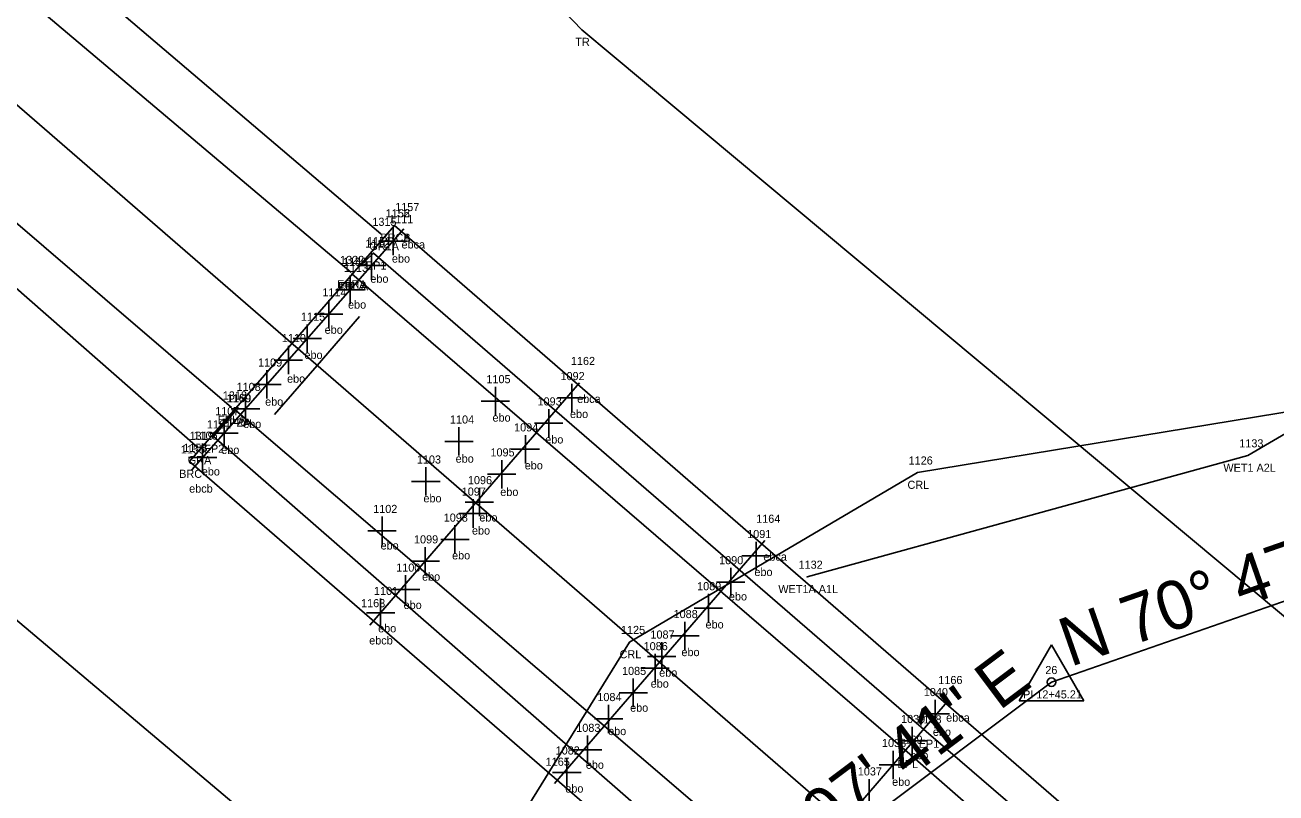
# Model space of a CAD drawing. Extents: x 2085293 to 2087464, y 876528 to 879458.
# Drawn here: x 2086332.2 to 2086486.4, y 878514.7 to 878609.3 of the extents above; entities that cross this region are included whole.
import ezdxf

# ---------------------------------------------------------------- set-up
doc = ezdxf.new("R2010")
doc.units = 0
for name, color, linetype in [('RD_EX_Bridge', 7, 'Continuous'), ('RD_EX_Bridge_txCode', 7, 'Continuous'), ('RD_EX_GuardRail', 7, 'Continuous'), ('RD_EX_GuardRail_txCode', 7, 'Continuous'), ('RD_EX_H2O', 7, 'Continuous'), ('RD_EX_H2O_txCode', 7, 'Continuous'), ('RD_EX_H2O_WetLd', 7, 'Continuous'), ('RD_EX_H2O_WetLd_txCode', 7, 'Continuous'), ('RD_EX_Misc', 7, 'Continuous'), ('RD_EX_Misc_txCode', 7, 'Continuous'), ('RD_EX_Road', 7, 'Continuous'), ('RD_EX_Road_txCode', 7, 'Continuous'), ('RD_EX_VEG', 7, 'Continuous'), ('RD_EX_VEG_txCode', 7, 'Continuous'), ('RD_HC_Cl', 7, 'Continuous'), ('RD_HC_Data', 7, 'Continuous'), ('RD_HC_Data_Tic', 7, 'Continuous'), ('RD_HC_txCode', 7, 'Continuous'), ('RD_SMD_Locator', 7, 'Continuous')]:
    doc.layers.add(name, color=color, linetype=linetype)

msp = doc.modelspace()

# ---------------------------------------------------------------- linework, layer by layer
at = {"layer": 'RD_EX_Bridge'}
msp.add_lwpolyline([(2086377.74, 878584.61), (2086559.01, 878427.4), (2086533.93, 878398.26), (2086352.47, 878555.51), (2086377.74, 878584.61)], dxfattribs=at)
at = {"layer": 'RD_EX_GuardRail'}
msp.add_line((2086353.55, 878557.19), (2086197.14, 878694.36), dxfattribs=at)
msp.add_lwpolyline([(2086376.08, 878583.56), (2086298.41, 878649.65), (2086246.79, 878694.55)], dxfattribs=at)
at = {"layer": 'RD_EX_H2O'}
msp.add_lwpolyline([(2086350.1, 878485.82), (2086392.62, 878510.5), (2086406.71, 878533.27), (2086442.18, 878554.15), (2086494.98, 878562.84), (2086530.51, 878595.43), (2086576.04, 878629.72), (2086651.92, 878628.48)], dxfattribs=at)
at = {"layer": 'RD_EX_H2O_WetLd'}
msp.add_lwpolyline([(2086428.59, 878541.31), (2086482.9, 878556.26), (2086496.03, 878563.96), (2086512.46, 878581.4)], dxfattribs=at)
at = {"layer": 'RD_EX_Misc'}
for p, q in [((2086378.89, 878584.18), (2086352.78, 878554.51)), ((2086377.57, 878584.43), (2086377.57, 878580.93)), ((2086374.93, 878581.43), (2086374.93, 878577.93)), ((2086379.32, 878582.68), (2086375.82, 878582.68)), ((2086372.29, 878578.43), (2086372.29, 878574.93)), ((2086376.68, 878579.68), (2086373.18, 878579.68)), ((2086369.64, 878575.42), (2086369.64, 878571.92)), ((2086374.04, 878576.68), (2086370.54, 878576.68)), ((2086367, 878572.42), (2086367, 878568.92)), ((2086371.39, 878573.67), (2086367.89, 878573.67)), ((2086368.75, 878570.67), (2086365.25, 878570.67)), ((2086364.68, 878569.78), (2086364.68, 878566.28)), ((2086366.43, 878568.03), (2086362.93, 878568.03)), ((2086362.03, 878566.77), (2086362.03, 878563.27)), ((2086363.78, 878565.02), (2086360.28, 878565.02)), ((2086400.56, 878565.21), (2086374.71, 878535.37)), ((2086390.18, 878564.72), (2086390.18, 878561.22)), ((2086399.59, 878565.1), (2086399.59, 878561.6)), ((2086359.39, 878563.77), (2086359.39, 878560.27)), ((2086391.93, 878562.97), (2086388.43, 878562.97)), ((2086401.34, 878563.35), (2086397.84, 878563.35)), ((2086361.14, 878562.02), (2086357.64, 878562.02)), ((2086396.75, 878561.98), (2086396.75, 878558.48)), ((2086356.75, 878560.77), (2086356.75, 878557.27)), ((2086398.5, 878560.23), (2086395, 878560.23)), ((2086358.5, 878559.02), (2086355, 878559.02)), ((2086385.69, 878559.75), (2086385.69, 878556.25)), ((2086393.87, 878558.78), (2086393.87, 878555.28)), ((2086354.11, 878557.76), (2086354.11, 878554.26)), ((2086387.44, 878558), (2086383.94, 878558)), ((2086395.62, 878557.03), (2086392.12, 878557.03)), ((2086355.86, 878556.01), (2086352.36, 878556.01)), ((2086390.96, 878555.7), (2086390.96, 878552.2)), ((2086381.61, 878554.82), (2086381.61, 878551.32)), ((2086392.71, 878553.95), (2086389.21, 878553.95)), ((2086383.36, 878553.07), (2086379.86, 878553.07)), ((2086388.2, 878552.28), (2086388.2, 878548.78)), ((2086387.42, 878550.87), (2086387.42, 878547.37)), ((2086389.17, 878549.12), (2086385.67, 878549.12)), ((2086389.95, 878550.53), (2086386.45, 878550.53)), ((2086376.22, 878548.73), (2086376.22, 878545.23)), ((2086385.2, 878547.66), (2086385.2, 878544.16)), ((2086377.97, 878546.98), (2086374.47, 878546.98)), ((2086381.53, 878544.98), (2086381.53, 878541.48)), ((2086386.95, 878545.91), (2086383.45, 878545.91)), ((2086423.39, 878545.77), (2086397.46, 878515.83)), ((2086422.3, 878545.64), (2086422.3, 878542.14)), ((2086383.28, 878543.23), (2086379.78, 878543.23)), ((2086424.05, 878543.89), (2086420.55, 878543.89)), ((2086379.11, 878541.5), (2086379.11, 878538)), ((2086419.17, 878542.41), (2086419.17, 878538.91)), ((2086420.92, 878540.66), (2086417.42, 878540.66)), ((2086376.04, 878538.63), (2086376.04, 878535.13)), ((2086380.86, 878539.75), (2086377.36, 878539.75)), ((2086416.42, 878539.21), (2086416.42, 878535.71)), ((2086377.79, 878536.88), (2086374.29, 878536.88)), ((2086418.17, 878537.46), (2086414.67, 878537.46)), ((2086413.52, 878535.78), (2086413.52, 878532.28)), ((2086415.27, 878534.03), (2086411.77, 878534.03)), ((2086410.67, 878533.25), (2086410.67, 878529.75)), ((2086412.42, 878531.5), (2086408.92, 878531.5)), ((2086409.85, 878531.82), (2086409.85, 878528.32)), ((2086411.6, 878530.07), (2086408.1, 878530.07)), ((2086407.16, 878528.77), (2086407.16, 878525.27)), ((2086408.91, 878527.02), (2086405.41, 878527.02)), ((2086444.38, 878526.17), (2086444.38, 878522.67)), ((2086404.13, 878525.55), (2086404.13, 878522.05)), ((2086445.86, 878525.9), (2086420.02, 878496.01)), ((2086446.13, 878524.42), (2086442.63, 878524.42)), ((2086405.88, 878523.8), (2086402.38, 878523.8)), ((2086441.54, 878522.85), (2086441.54, 878519.35)), ((2086401.53, 878521.76), (2086401.53, 878518.26)), ((2086403.28, 878520.01), (2086399.78, 878520.01)), ((2086439.2, 878519.89), (2086439.2, 878516.39)), ((2086443.29, 878521.1), (2086439.79, 878521.1)), ((2086398.98, 878518.97), (2086398.98, 878515.47)), ((2086400.73, 878517.22), (2086397.23, 878517.22)), ((2086440.95, 878518.14), (2086437.45, 878518.14)), ((2086436.22, 878516.39), (2086436.22, 878512.89))]:
    msp.add_line(p, q, dxfattribs=at)
at = {"layer": 'RD_EX_Road'}
for points in [[(2086372.38, 878578.86), (2086293.83, 878645.12), (2086244.36, 878687.63), (2086202.39, 878723.25), (2086166.57, 878755.93), (2086121.04, 878795), (2086040.83, 878865.43), (2085975.87, 878922.08), (2085950.22, 878944.06), (2085880.76, 879003.91), (2085804.88, 879069.53), (2085722.05, 879140.46), (2085671.69, 879184.07), (2085652.93, 879200.33), (2085629.96, 879220.25)], [(2086357.65, 878562.16), (2086280.16, 878628.67), (2086188.35, 878708.55), (2086107.57, 878779.2), (2086026.47, 878849.35), (2085949.01, 878917.79), (2085867.99, 878987.21), (2085809.89, 879037.77), (2085792.99, 879052.21), (2085710.02, 879123.37), (2085618.43, 879202.89)], [(2086372.48, 878578.63), (2086375.14, 878581.18), (2086443.25, 878522.25), (2086511.37, 878463.55), (2086556.66, 878424.84), (2086553.57, 878421.17)], [(2086372.48, 878578.63), (2086440.93, 878519.74), (2086508.75, 878460.4), (2086553.57, 878421.17), (2086626.32, 878357.37), (2086700.27, 878293.03), (2086782.28, 878221.68)], [(2086358.19, 878561.82), (2086355.45, 878558.6), (2086422.99, 878499.64), (2086491.68, 878440.33), (2086536.87, 878401.71), (2086539.89, 878405.13)], [(2086358.19, 878561.82), (2086426.45, 878503.36), (2086494.99, 878444.26), (2086539.89, 878405.13), (2086612.82, 878341.2), (2086686.27, 878277.41), (2086769.9, 878205.27), (2086844.45, 878140.34), (2086932.82, 878063.42), (2086964.75, 878034.46), (2087001.42, 877999.16), (2087042.78, 877955.43), (2087078.39, 877914.63), (2087110.34, 877876.43), (2087140.35, 877836.91), (2087173.38, 877789.29), (2087206.69, 877736.44), (2087236.08, 877683.18), (2087259.17, 877638.22), (2087287.12, 877578.12)]]:
    msp.add_lwpolyline(points, dxfattribs=at)
at = {"layer": 'RD_EX_VEG'}
for points in [[(2086498.28, 878394.88), (2086329.73, 878537.22), (2086212.13, 878664.14), (2086102.42, 878763.92), (2085939.19, 878906.04), (2085793.62, 879021.84)], [(2086569.24, 878468.04), (2086400.81, 878608.73), (2086323.2, 878689.41), (2086335.21, 878726.99)]]:
    msp.add_lwpolyline(points, dxfattribs=at)
at = {"layer": 'RD_HC_Cl'}
for p, q in [((2086923.31, 878086.15), (2085624.78, 879211.84)), ((2086458.69, 878528.33), (2086516.79, 878548.57)), ((2086413.25, 878494.25), (2086458.69, 878528.33))]:
    msp.add_line(p, q, dxfattribs=at)
at = {"layer": 'RD_HC_Data'}
for p, q in [((2086454.72, 878526.04), (2086458.69, 878532.92)), ((2086458.69, 878532.92), (2086462.66, 878526.04)), ((2086454.72, 878526.04), (2086462.66, 878526.04))]:
    msp.add_line(p, q, dxfattribs=at)
msp.add_circle((2086458.69, 878528.33), 0.529, dxfattribs=at)
at = {"layer": 'RD_HC_Data_Tic'}
for q in [(2086373.44, 878573.41), (2086362.96, 878561.32)]:
    msp.add_line((2086368.2, 878567.37), q, dxfattribs=at)
at = {"layer": 'RD_SMD_Locator'}
for centre in [(2086400.81, 878608.73), (2086377.74, 878584.61), (2086377.74, 878584.61), (2086376.08, 878583.56), (2086375.14, 878581.18), (2086372.38, 878578.86), (2086372.48, 878578.63), (2086372.48, 878578.63), (2086357.65, 878562.16), (2086358.19, 878561.82), (2086358.19, 878561.82), (2086355.45, 878558.6), (2086353.55, 878557.19), (2086352.47, 878555.51), (2086482.9, 878556.26), (2086442.18, 878554.15), (2086428.59, 878541.31), (2086406.71, 878533.27), (2086458.69, 878528.33), (2086443.25, 878522.25), (2086440.93, 878519.74)]:
    msp.add_circle(centre, 0.001, dxfattribs=at)

# ---------------------------------------------------------------- texts
at = {"layer": 'RD_EX_Bridge_txCode'}
for s, p in [('1156', (2086376.65, 878585.61)), ('1152', (2086376.67, 878585.61)), ('BRCA', (2086376, 878582.61)), ('BRCB', (2086376.01, 878582.61)), ('1155', (2086351.41, 878556.51)), ('BRC', (2086351.22, 878553.51))]:
    msp.add_text(s, height=1, dxfattribs=at).set_placement(p)
at = {"layer": 'RD_EX_GuardRail_txCode'}
for s, p in [('1315', (2086375.02, 878584.56)), ('GR1A', (2086374.65, 878581.56)), ('1319', (2086352.49, 878558.19)), ('GRA', (2086352.28, 878555.19))]:
    msp.add_text(s, height=1, dxfattribs=at).set_placement(p)
at = {"layer": 'RD_EX_H2O_txCode'}
for s, p in [('1126', (2086441.09, 878555.15)), ('CRL', (2086440.95, 878552.15)), ('1125', (2086405.65, 878534.27)), ('CRL', (2086405.48, 878531.27))]:
    msp.add_text(s, height=1, dxfattribs=at).set_placement(p)
at = {"layer": 'RD_EX_H2O_WetLd_txCode'}
for s, p in [('1133', (2086481.83, 878557.26)), ('WET1 A2L', (2086479.87, 878554.26)), ('1132', (2086427.53, 878542.31)), ('WET1A A1L', (2086425.04, 878539.31))]:
    msp.add_text(s, height=1, dxfattribs=at).set_placement(p)
at = {"layer": 'RD_EX_Misc_txCode'}
for s, p in [('1157', (2086377.83, 878586.38)), ('1111', (2086377.08, 878584.88)), ('1112', (2086374.15, 878581.88)), ('ebca', (2086378.61, 878581.77)), ('1113', (2086371.51, 878578.88)), ('ebo', (2086377.43, 878580.03)), ('ebo', (2086374.77, 878577.55)), ('1114', (2086368.86, 878575.87)), ('ebo', (2086372.02, 878574.36)), ('1115', (2086366.22, 878572.87)), ('ebo', (2086369.14, 878571.26)), ('1110', (2086363.86, 878570.23)), ('ebo', (2086366.65, 878568.16)), ('1109', (2086360.93, 878567.22)), ('1162', (2086399.48, 878567.41)), ('ebo', (2086364.51, 878565.23)), ('1105', (2086389.07, 878565.17)), ('1092', (2086398.2, 878565.55)), ('1108', (2086358.29, 878564.22)), ('ebo', (2086361.81, 878562.4)), ('1093', (2086395.37, 878562.43)), ('ebca', (2086400.25, 878562.74)), ('1107', (2086355.65, 878561.22)), ('ebo', (2086389.82, 878560.44)), ('ebo', (2086399.37, 878560.88)), ('ebo', (2086359.1, 878559.65)), ('1104', (2086384.58, 878560.2)), ('1094', (2086392.48, 878559.23)), ('1106', (2086352.98, 878558.21)), ('ebo', (2086396.32, 878557.74)), ('1158', (2086351.72, 878556.71)), ('ebo', (2086356.4, 878556.46)), ('1095', (2086389.57, 878556.15)), ('1103', (2086380.5, 878555.27)), ('ebo', (2086385.28, 878555.38)), ('ebo', (2086393.79, 878554.55)), ('ebo', (2086354, 878553.8)), ('1096', (2086386.79, 878552.73)), ('ebcb', (2086352.45, 878551.69)), ('1097', (2086386.03, 878551.32)), ('ebo', (2086390.78, 878551.28)), ('ebo', (2086381.31, 878550.49)), ('1102', (2086375.12, 878549.18)), ('1098', (2086383.81, 878548.11)), ('ebo', (2086388.2, 878548.13)), ('ebo', (2086387.29, 878546.52)), ('1164', (2086422.31, 878547.97)), ('1099', (2086380.15, 878545.43)), ('1091', (2086421.2, 878546.09)), ('ebo', (2086376.03, 878544.68)), ('ebo', (2086384.84, 878543.46)), ('1100', (2086377.96, 878541.95)), ('1090', (2086417.74, 878542.86)), ('ebca', (2086423.19, 878543.3)), ('ebo', (2086381.14, 878540.84)), ('ebo', (2086422.09, 878541.41)), ('1101', (2086375.22, 878539.08)), ('1089', (2086415.03, 878539.66)), ('1163', (2086373.63, 878537.57)), ('ebo', (2086378.87, 878537.35)), ('ebo', (2086418.95, 878538.4)), ('1088', (2086412.13, 878536.23)), ('ebo', (2086375.73, 878534.47)), ('ebo', (2086416.07, 878534.95)), ('ebcb', (2086374.63, 878532.98)), ('1087', (2086409.28, 878533.7)), ('1086', (2086408.44, 878532.27)), ('ebo', (2086413.1, 878531.54)), ('1085', (2086405.78, 878529.22)), ('ebo', (2086410.36, 878529.01)), ('1166', (2086444.75, 878528.1)), ('ebo', (2086409.31, 878527.66)), ('1040', (2086442.96, 878526.62)), ('1084', (2086402.74, 878526)), ('ebo', (2086406.78, 878524.69)), ('ebca', (2086445.72, 878523.47)), ('1083', (2086400.14, 878522.21)), ('ebo', (2086404.07, 878521.81)), ('1039', (2086440.16, 878523.3)), ('1038', (2086437.81, 878520.34)), ('ebo', (2086444.08, 878521.72)), ('1082', (2086397.6, 878519.42)), ('ebo', (2086441.29, 878518.84)), ('1165', (2086396.37, 878518.03)), ('ebo', (2086401.32, 878517.66)), ('1037', (2086434.83, 878516.84)), ('ebo', (2086398.79, 878514.73)), ('ebo', (2086439.06, 878515.56))]:
    msp.add_text(s, height=1, dxfattribs=at).set_placement(p)
at = {"layer": 'RD_EX_Road_txCode'}
for s, p in [('1151', (2086374.36, 878582.18)), ('1322', (2086371.04, 878579.86)), ('1150', (2086371.38, 878579.63)), ('1149', (2086371.42, 878579.63)), ('EP1', (2086374.22, 878579.18)), ('EPRA', (2086370.67, 878576.86)), ('EPLA', (2086370.79, 878576.63)), ('EP1A', (2086371.07, 878576.63)), ('1318', (2086356.59, 878563.16)), ('1160', (2086357.06, 878562.82)), ('1159', (2086357.13, 878562.82)), ('1161', (2086354.64, 878559.6)), ('EPLA', (2086355.96, 878560.16)), ('EPRA', (2086356.47, 878559.82)), ('EP2A', (2086356.5, 878559.82)), ('EP2', (2086354.24, 878556.6)), ('1168', (2086442.17, 878523.25)), ('1169', (2086439.84, 878520.74)), ('EP1', (2086442.33, 878520.25)), ('EPL', (2086439.73, 878517.74))]:
    msp.add_text(s, height=1, dxfattribs=at).set_placement(p)
at = {"layer": 'RD_EX_VEG_txCode'}
msp.add_text('TR', height=1, dxfattribs=at).set_placement((2086400.02, 878606.73))
at = {"layer": 'RD_HC_Data'}
for s, rotation, p in [('N 70%%d 47\' 53" E', 19.2019, (2086460.99, 878530.19)), ('N 53%%d 07\' 41" E', 36.8718, (2086412.99, 878495.3))]:
    msp.add_text(s, height=6, rotation=rotation, dxfattribs=at).set_placement(p)
at = {"layer": 'RD_HC_txCode'}
for s, p in [('26', (2086457.93, 878529.33)), ('PI 12+45.21', (2086455.19, 878526.33))]:
    msp.add_text(s, height=1, dxfattribs=at).set_placement(p)

doc.saveas('drawing.dxf')
